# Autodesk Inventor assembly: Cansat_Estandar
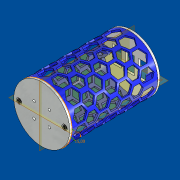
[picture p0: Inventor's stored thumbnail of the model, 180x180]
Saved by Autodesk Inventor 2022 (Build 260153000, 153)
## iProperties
Created: 2022-06
Part Number: Cansat_Estandar
Document SubType Name: Assembly
Designer: pined
Author: pined
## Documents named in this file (9)
- G:\Unidades compartidas\PROYECTO PANAMA\Archivos para pagina web\Cansat_Estandar\Cansat_Estandar.iam
- G:\Unidades compartidas\PROYECTO PANAMA\Archivos para pagina web\Cansat_Estandar\Case_Cansat Estandar.ipt
- G:\Unidades compartidas\PROYECTO PANAMA\Archivos para pagina web\Cansat_Estandar\Tapa CanSat cerrado.ipt
- G:\Unidades compartidas\PROYECTO PANAMA\Archivos para pagina web\Cansat_Estandar\Tapa para exp externo.ipt
- D:\Documents\Inventor\Content Center Files\R2022\es-ES\AS 1112 (2)\AS 1112 - M3  Tipo 10.ipt
- D:\Documents\Inventor\Content Center Files\R2022\es-ES\AS 1112 (2)\AS 1112 - M2,5  Tipo 10.ipt
- G:\Unidades compartidas\PROYECTO PANAMA\Archivos para pagina web\Cansat_Estandar\Arandela.ipt
- G:\Unidades compartidas\PROYECTO PANAMA\Archivos para pagina web\Cansat_Estandar\Soporte tuercas.ipt
- D:\Documents\Inventor\Content Center Files\R2022\es-ES\AS 1427(04)\AS 1427 - M2,5 x 8(5) I.ipt
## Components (17 placed, 8 different names)
1. Case_Cansat Estandar:1 — Coincidencia:1, Coincidencia:2, Nivelación:1, Coincidencia:3, Coincidencia:4, Nivelación:2, Coincidencia:5, Coincidencia:6, Nivelación:3, Coincidencia:7, Coincidencia:8, Nivelación:4, Coincidencia:9, Coincidencia:25, Coincidencia:26, Coincidencia:27, Coincidencia:28
2. AS 1112 (2) - Métrico M3  Tipo 10:1 — Coincidencia:17, Coincidencia:18, Nivelación:5
3. AS 1112 (2) - Métrico M3  Tipo 10:3 — Coincidencia:23, Coincidencia:24, Nivelación:8
4. AS 1112 (2) - Métrico M3  Tipo 10:4 — Coincidencia:21, Coincidencia:22, Nivelación:7
5. AS 1112 (2) - Métrico M3  Tipo 10:5 — Coincidencia:19, Coincidencia:20, Nivelación:6
6. AS 1112 (2) - Métrico M2,5  Tipo 10:1 — Coincidencia:1, Coincidencia:2, Nivelación:1, Coincidencia:11, Coincidencia:30
7. AS 1112 (2) - Métrico M2,5  Tipo 10:2 — Coincidencia:3, Coincidencia:4, Nivelación:2, Coincidencia:10, Coincidencia:29
8. AS 1112 (2) - Métrico M2,5  Tipo 10:3 — Coincidencia:7, Coincidencia:8, Nivelación:4
9. AS 1112 (2) - Métrico M2,5  Tipo 10:4 — Coincidencia:5, Coincidencia:6, Nivelación:3
10. Arandela:1 — Coincidencia:12, Coincidencia:13, Coincidencia:14, Coincidencia:15, Coincidencia:16, Coincidencia:17, Coincidencia:19, Coincidencia:21, Coincidencia:23
11. Tapa para exp externo:1 — Coincidencia:12, Coincidencia:13, Coincidencia:14, Coincidencia:25, Coincidencia:26, Coincidencia:27, Coincidencia:28, Coincidencia:31, Nivelación:11, Coincidencia:32, Nivelación:12
12. Tapa CanSat cerrado:1 — Coincidencia:9, Coincidencia:10, Coincidencia:11, Nivelación:9, Nivelación:10
13. Soporte tuercas:1 — Coincidencia:15, Coincidencia:16, Coincidencia:18, Nivelación:5, Coincidencia:20, Nivelación:6, Coincidencia:22, Nivelación:7, Coincidencia:24, Nivelación:8
14. AS 1427 H - Métrico M2,5 x 8:1 — Coincidencia:31, Nivelación:11
15. AS 1427 H - Métrico M2,5 x 8:2 — Coincidencia:30, Nivelación:10
16. AS 1427 H - Métrico M2,5 x 8:3 — Coincidencia:29, Nivelación:9
17. AS 1427 H - Métrico M2,5 x 8:4 — Coincidencia:32, Nivelación:12
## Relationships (44: Mate 32, Flush 12)
- Coincidencia:1 [Mate]: Case_Cansat Estandar:1 ↔ AS 1112 (2) - Métrico M2,5  Tipo 10:1
- Coincidencia:2 [Mate]: Case_Cansat Estandar:1 ↔ AS 1112 (2) - Métrico M2,5  Tipo 10:1
- Nivelación:1 [Flush]: Case_Cansat Estandar:1 ↔ AS 1112 (2) - Métrico M2,5  Tipo 10:1
- Coincidencia:3 [Mate]: Case_Cansat Estandar:1 ↔ AS 1112 (2) - Métrico M2,5  Tipo 10:2
- Coincidencia:4 [Mate]: Case_Cansat Estandar:1 ↔ AS 1112 (2) - Métrico M2,5  Tipo 10:2
- Nivelación:2 [Flush]: Case_Cansat Estandar:1 ↔ AS 1112 (2) - Métrico M2,5  Tipo 10:2
- Coincidencia:5 [Mate]: Case_Cansat Estandar:1 ↔ AS 1112 (2) - Métrico M2,5  Tipo 10:4
- Coincidencia:6 [Mate]: Case_Cansat Estandar:1 ↔ AS 1112 (2) - Métrico M2,5  Tipo 10:4
- Nivelación:3 [Flush]: Case_Cansat Estandar:1 ↔ AS 1112 (2) - Métrico M2,5  Tipo 10:4
- Coincidencia:7 [Mate]: Case_Cansat Estandar:1 ↔ AS 1112 (2) - Métrico M2,5  Tipo 10:3
- Coincidencia:8 [Mate]: Case_Cansat Estandar:1 ↔ AS 1112 (2) - Métrico M2,5  Tipo 10:3
- Nivelación:4 [Flush]: Case_Cansat Estandar:1 ↔ AS 1112 (2) - Métrico M2,5  Tipo 10:3
- Coincidencia:9 [Mate]: Case_Cansat Estandar:1 ↔ Tapa CanSat cerrado:1
- Coincidencia:10 [Mate]: AS 1112 (2) - Métrico M2,5  Tipo 10:2 ↔ Tapa CanSat cerrado:1
- Coincidencia:11 [Mate]: AS 1112 (2) - Métrico M2,5  Tipo 10:1 ↔ Tapa CanSat cerrado:1
- Coincidencia:12 [Mate]: Arandela:1 ↔ Tapa para exp externo:1
- Coincidencia:13 [Mate]: Arandela:1 ↔ Tapa para exp externo:1
- Coincidencia:14 [Mate]: Arandela:1 ↔ Tapa para exp externo:1
- Coincidencia:15 [Mate]: Arandela:1 ↔ Soporte tuercas:1
- Coincidencia:16 [Mate]: Arandela:1 ↔ Soporte tuercas:1
- Coincidencia:17 [Mate]: AS 1112 (2) - Métrico M3  Tipo 10:1 ↔ Arandela:1
- Coincidencia:18 [Mate]: AS 1112 (2) - Métrico M3  Tipo 10:1 ↔ Soporte tuercas:1
- Nivelación:5 [Flush]: AS 1112 (2) - Métrico M3  Tipo 10:1 ↔ Soporte tuercas:1
- Coincidencia:19 [Mate]: AS 1112 (2) - Métrico M3  Tipo 10:5 ↔ Arandela:1
- Coincidencia:20 [Mate]: AS 1112 (2) - Métrico M3  Tipo 10:5 ↔ Soporte tuercas:1
- Nivelación:6 [Flush]: AS 1112 (2) - Métrico M3  Tipo 10:5 ↔ Soporte tuercas:1
- Coincidencia:21 [Mate]: AS 1112 (2) - Métrico M3  Tipo 10:4 ↔ Arandela:1
- Coincidencia:22 [Mate]: AS 1112 (2) - Métrico M3  Tipo 10:4 ↔ Soporte tuercas:1
- Nivelación:7 [Flush]: AS 1112 (2) - Métrico M3  Tipo 10:4 ↔ Soporte tuercas:1
- Coincidencia:23 [Mate]: AS 1112 (2) - Métrico M3  Tipo 10:3 ↔ Arandela:1
- Coincidencia:24 [Mate]: AS 1112 (2) - Métrico M3  Tipo 10:3 ↔ Soporte tuercas:1
- Nivelación:8 [Flush]: AS 1112 (2) - Métrico M3  Tipo 10:3 ↔ Soporte tuercas:1
- Coincidencia:25 [Mate]: Case_Cansat Estandar:1 ↔ Tapa para exp externo:1
- Coincidencia:26 [Mate]: Case_Cansat Estandar:1 ↔ Tapa para exp externo:1
- Coincidencia:27 [Mate]: Case_Cansat Estandar:1 ↔ Tapa para exp externo:1
- Coincidencia:28 [Mate]: Case_Cansat Estandar:1 ↔ Tapa para exp externo:1
- Coincidencia:29 [Mate]: AS 1112 (2) - Métrico M2,5  Tipo 10:2 ↔ AS 1427 H - Métrico M2,5 x 8:3
- Nivelación:9 [Flush]: Tapa CanSat cerrado:1 ↔ AS 1427 H - Métrico M2,5 x 8:3
- Coincidencia:30 [Mate]: AS 1112 (2) - Métrico M2,5  Tipo 10:1 ↔ AS 1427 H - Métrico M2,5 x 8:2
- Nivelación:10 [Flush]: Tapa CanSat cerrado:1 ↔ AS 1427 H - Métrico M2,5 x 8:2
- Coincidencia:31 [Mate]: Tapa para exp externo:1 ↔ AS 1427 H - Métrico M2,5 x 8:1
- Nivelación:11 [Flush]: Tapa para exp externo:1 ↔ AS 1427 H - Métrico M2,5 x 8:1
- Coincidencia:32 [Mate]: Tapa para exp externo:1 ↔ AS 1427 H - Métrico M2,5 x 8:4
- Nivelación:12 [Flush]: Tapa para exp externo:1 ↔ AS 1427 H - Métrico M2,5 x 8:4
